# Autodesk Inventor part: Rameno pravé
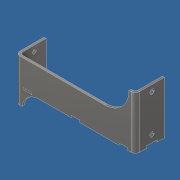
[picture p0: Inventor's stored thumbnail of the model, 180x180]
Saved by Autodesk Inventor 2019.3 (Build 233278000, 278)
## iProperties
Created: 2019-02
Part Number: Rameno pravé
Material: Nerezová ocel, austenitická
Document SubType Name: Plech
Designer: B-hon
Density: 8 g/cm^3
Sheet Metal Rule: Výchozí_mm
Appearance: Pololeštěná
Author: B-hon
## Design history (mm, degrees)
node "Plocha3"
  sketch "Náčrt4"
    geometry: L1 (0, 0)-(169, 0); L2 (169, 0)-(169, 95); L3 (169, 95)-(0, 95); L4 (0, 95)-(0, 0)
    constraints: 8 end point, 2 parallel, 1 horizontal, 1 perpendicular
    dimensions: "d21" = 169 distance of L3.end L2.end; "d22" = 95 distance of L2.end L1.end
node "Obruba2"
node "Obruba3"
sketch "Náčrt7"
  geometry: L1 (-8.449, 60)-(-3.667, 60); L2 (-3.667, 60)-(-3.667, 60); L3 (-3.667, 60)-(160, 60); L4 (160, 60)-(160, 100.088); L5 (160, 100.088)-(-8.679, 99.094); L6 (-8.679, 99.094)-(-8.449, 60); L7 (6, 95)-(6, 0) reference; L8 (163, 0)-(163, 95) reference; L9 (163, 0)-(6, 0) reference; 1 further point
  constraints: 12 end point, 4 perpendicular, 1 horizontal
  dimensions: "d45" = 3 distance between parallel lines of L8 L4; "d46" = 60 distance between parallel lines of L9 L3; "d47" = 60 distance between parallel lines of L9 L1
extrude "Vysunutí1" cut sketch "Náčrt7" distance "d48" = 100; taper "d49" = 0 deg
fillet "Zaoblení2" dims "d51" = 35
sketch "Náčrt8"
  geometry: L1 (9, 21)-(200.584, 21); L2 (200.584, 21)-(200.584, -6.662); L3 (200.584, -6.662)-(9, -6.662); L4 (9, -6.662)-(9, 21); L5 (125, 60)-(6, 60) reference; L6 (6, 60)-(6, 0) reference; 1 further point
  constraints: 8 end point, 2 parallel, 1 horizontal, 1 perpendicular
  dimensions: "d52" = 39 distance between parallel lines of L5 L1; "d53" = 3 distance between parallel lines of L6 L4
extrude "Vysunutí2" cut sketch "Náčrt8" distance "d54" = 100; taper "d55" = 0 deg
fillet "Zaoblení3" dims "d56" = 25
sketch "Náčrt9"
  geometry: L1 (0, 0)-(0, 60) reference; L2 (34, 0)-(0, 0) reference; 4 further points
  constraints: 1 horizontal alignment
  dimensions: "d57" = 6 distance from line of L1 point (6, 7); "d58" = 21 distance of point (27, 7) point (6, 7); "d59" = 7 distance from line of L2 point (6, 7); "d60" = 45 vertical distance of point (27, 7) point (16.5, 52); "d61" = 10.5 horizontal distance of point (27, 7) point (16.5, 52) (= 0.5 x d58)
hole "Díra1" sketch "Náčrt9" at (16.5, 52), (27, 7), (6, 7) diameter "d62" = 5.5; stored, may be unused: countersink angle "d66" = 90 deg, drill point angle "d68" = 118 deg; dims "d63" = 12, "d64" = 4, "d65" = 2, "d67" = 3 (= Tloušťka)
sketch "Náčrt10"
  geometry: L1 (0, 0)-(35, 0) reference; C1 r 2.75 at (28, -88) reference; C2 r 2.75 at (7, -88) reference; C3 r 2.75 at (17.5, -43) reference; 3 further points
  constraints: 2 vertical alignment
  dimensions: "d69" = 9 distance from line of point (17.5, -9) L1; "d70" = 52 distance of point (17.5, -61) point (17.5, -9)
hole "Díra2" sketch "Náčrt10" at (17.5, -61), (17.5, -9) diameter "d71" = 6.6; stored, may be unused: countersink angle "d75" = 90 deg, drill point angle "d77" = 118 deg; dims "d72" = 12, "d73" = 4, "d74" = 2, "d76" = 3 (= Tloušťka)
sketch "Náčrt15"
  geometry: L1 (-163, 21)-(-33.678, 21) reference; L2 (-158, 24)-(-146, 24); L3 (-146, 24)-(-146, 21); L4 (-146, 21)-(-158, 21); L5 (-158, 21)-(-158, 24); L6 (-163, 95)-(-163, 21) reference; 1 further point
  constraints: 8 end point, 2 parallel, 1 horizontal, 1 perpendicular, 1 point on line
  dimensions: "d104" = 12 distance of L3.end L4.end; "d105" = 3 distance of L2.end L3.end; "d106" = 5 distance between parallel lines of L6 L5
extrude "Vysunutí7" cut sketch "Náčrt15" distance "d107" = 300; taper "d108" = 0 deg
pattern_linear "Obdélníkové pole3" dims "d111" = 67.5
sketch "Náčrt16"
  geometry: L1 (10, -71)-(25, -71); L2 (25, -71)-(25, -74); L3 (25, -74)-(10, -74); L4 (10, -74)-(10, -71); L5 (0, -74)-(35, -74) reference; L6 (-6, -74)-(-6, 0) reference; 1 further point
  constraints: 8 end point, 2 parallel, 1 horizontal, 1 perpendicular
  dimensions: "d112" = 0 distance between parallel lines of L5 L3; "d113" = 3 distance of L1.end L2.end; "d114" = 15 distance of L2.end L3.end; "d115" = 16 distance between parallel lines of L6 L4
extrude "Vysunutí8" cut sketch "Náčrt16" distance "d116" = 300; taper "d117" = 0 deg
node "Těleso3"
feature "Deska4" dims "d23" = 3 (= Tloušťka)
sketch "Náčrt5"
  geometry: L1 through (47.5, 0) direction (-1, 0); L2 through (0, -20) direction (0, -1); L3 (0, -40)-(95, -40); L4 (95, -40)-(95, 0)
  constraints: 6 end point, 1 horizontal, 1 perpendicular, 1 vertical
feature "Deska5" dims "d23" = 3 (= Tloušťka), "d24" = 3 (= ŠířkaVýštipu), "d25" = 1.5 (= HloubkaVýštipu), "d26" = 6 (= MinimálníZbytek), "d27" = 3 (= PřechodovýPoloměr), "d28" = 40, "d29" = 90 deg, "d30" = 3 (= PoloměrOhybu), "d31" = 12 (= VelikostRohovéhoVýštipu), "d32" = 3 (= VelikostMezery), "d33" = 3 (= VelikostJacobihoPoloměru), "MezeraVystřižení" = 0.01
feature "Ohyb2" dims "d23" = 3 (= Tloušťka), "d24" = 3 (= ŠířkaVýštipu), "d25" = 1.5 (= HloubkaVýštipu), "d26" = 6 (= MinimálníZbytek), "d27" = 3 (= PřechodovýPoloměr), "d28" = 40, "d29" = 90 deg, "d30" = 3 (= PoloměrOhybu), "MezeraVystřižení" = 0.01
feature "Roh2" dims "d28" = 40, "d29" = 90 deg, "d31" = 12 (= VelikostRohovéhoVýštipu), "d32" = 3 (= VelikostMezery), "d33" = 3 (= VelikostJacobihoPoloměru)
sketch "Náčrt6"
  geometry: L1 through (47.5, 0) direction (-1, 0); L2 through (0, -20.5) direction (2.41e-32, -1); L3 (0, -41)-(95, -41); L4 (95, -41)-(95, 0)
  constraints: 6 end point, 1 horizontal, 1 perpendicular, 1 vertical
feature "Deska6" dims "d23" = 3 (= Tloušťka), "d34" = 3 (= ŠířkaVýštipu), "d35" = 1.5 (= HloubkaVýštipu), "d36" = 6 (= MinimálníZbytek), "d37" = 3 (= PřechodovýPoloměr), "d38" = 41, "d39" = 90 deg, "d40" = 3 (= PoloměrOhybu), "d41" = 12 (= VelikostRohovéhoVýštipu), "d42" = 3 (= VelikostMezery), "d43" = 3 (= VelikostJacobihoPoloměru), "MezeraVystřižení" = 0.01
feature "Ohyb3" dims "d23" = 3 (= Tloušťka), "d34" = 3 (= ŠířkaVýštipu), "d35" = 1.5 (= HloubkaVýštipu), "d36" = 6 (= MinimálníZbytek), "d37" = 3 (= PřechodovýPoloměr), "d38" = 41, "d39" = 90 deg, "d40" = 3 (= PoloměrOhybu), "MezeraVystřižení" = 0.01
feature "Roh3" dims "d38" = 41, "d39" = 90 deg, "d41" = 12 (= VelikostRohovéhoVýštipu), "d42" = 3 (= VelikostMezery), "d43" = 3 (= VelikostJacobihoPoloměru)
other parameters: "Tloušťka" = 3 (derived), "KSoučinitel" = 4.4, "PoloměrOhybu" = 3 (= Tloušťka), "ŠířkaVýštipu" = 3 (= Tloušťka), "HloubkaVýštipu" = 1.5 (= 0.5 x Tloušťka), "VelikostRohovéhoVýštipu" = 12 (= 4 x Tloušťka), "MinimálníZbytek" = 6 (= 2 x Tloušťka), "PřechodovýPoloměr" = 3 (= PoloměrOhybu), "VelikostJacobihoPoloměru" = 3 (= PoloměrOhybu), "VelikostMezery" = 3 (= Tloušťka)
